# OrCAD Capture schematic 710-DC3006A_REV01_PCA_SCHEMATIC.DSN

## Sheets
1 PAGE1: company: ANALOG DEVICES; note: DEMO BOARD BILL OF MATERIALS; note: NO-OPTO ISOLATED FLYBACK CONVERTER
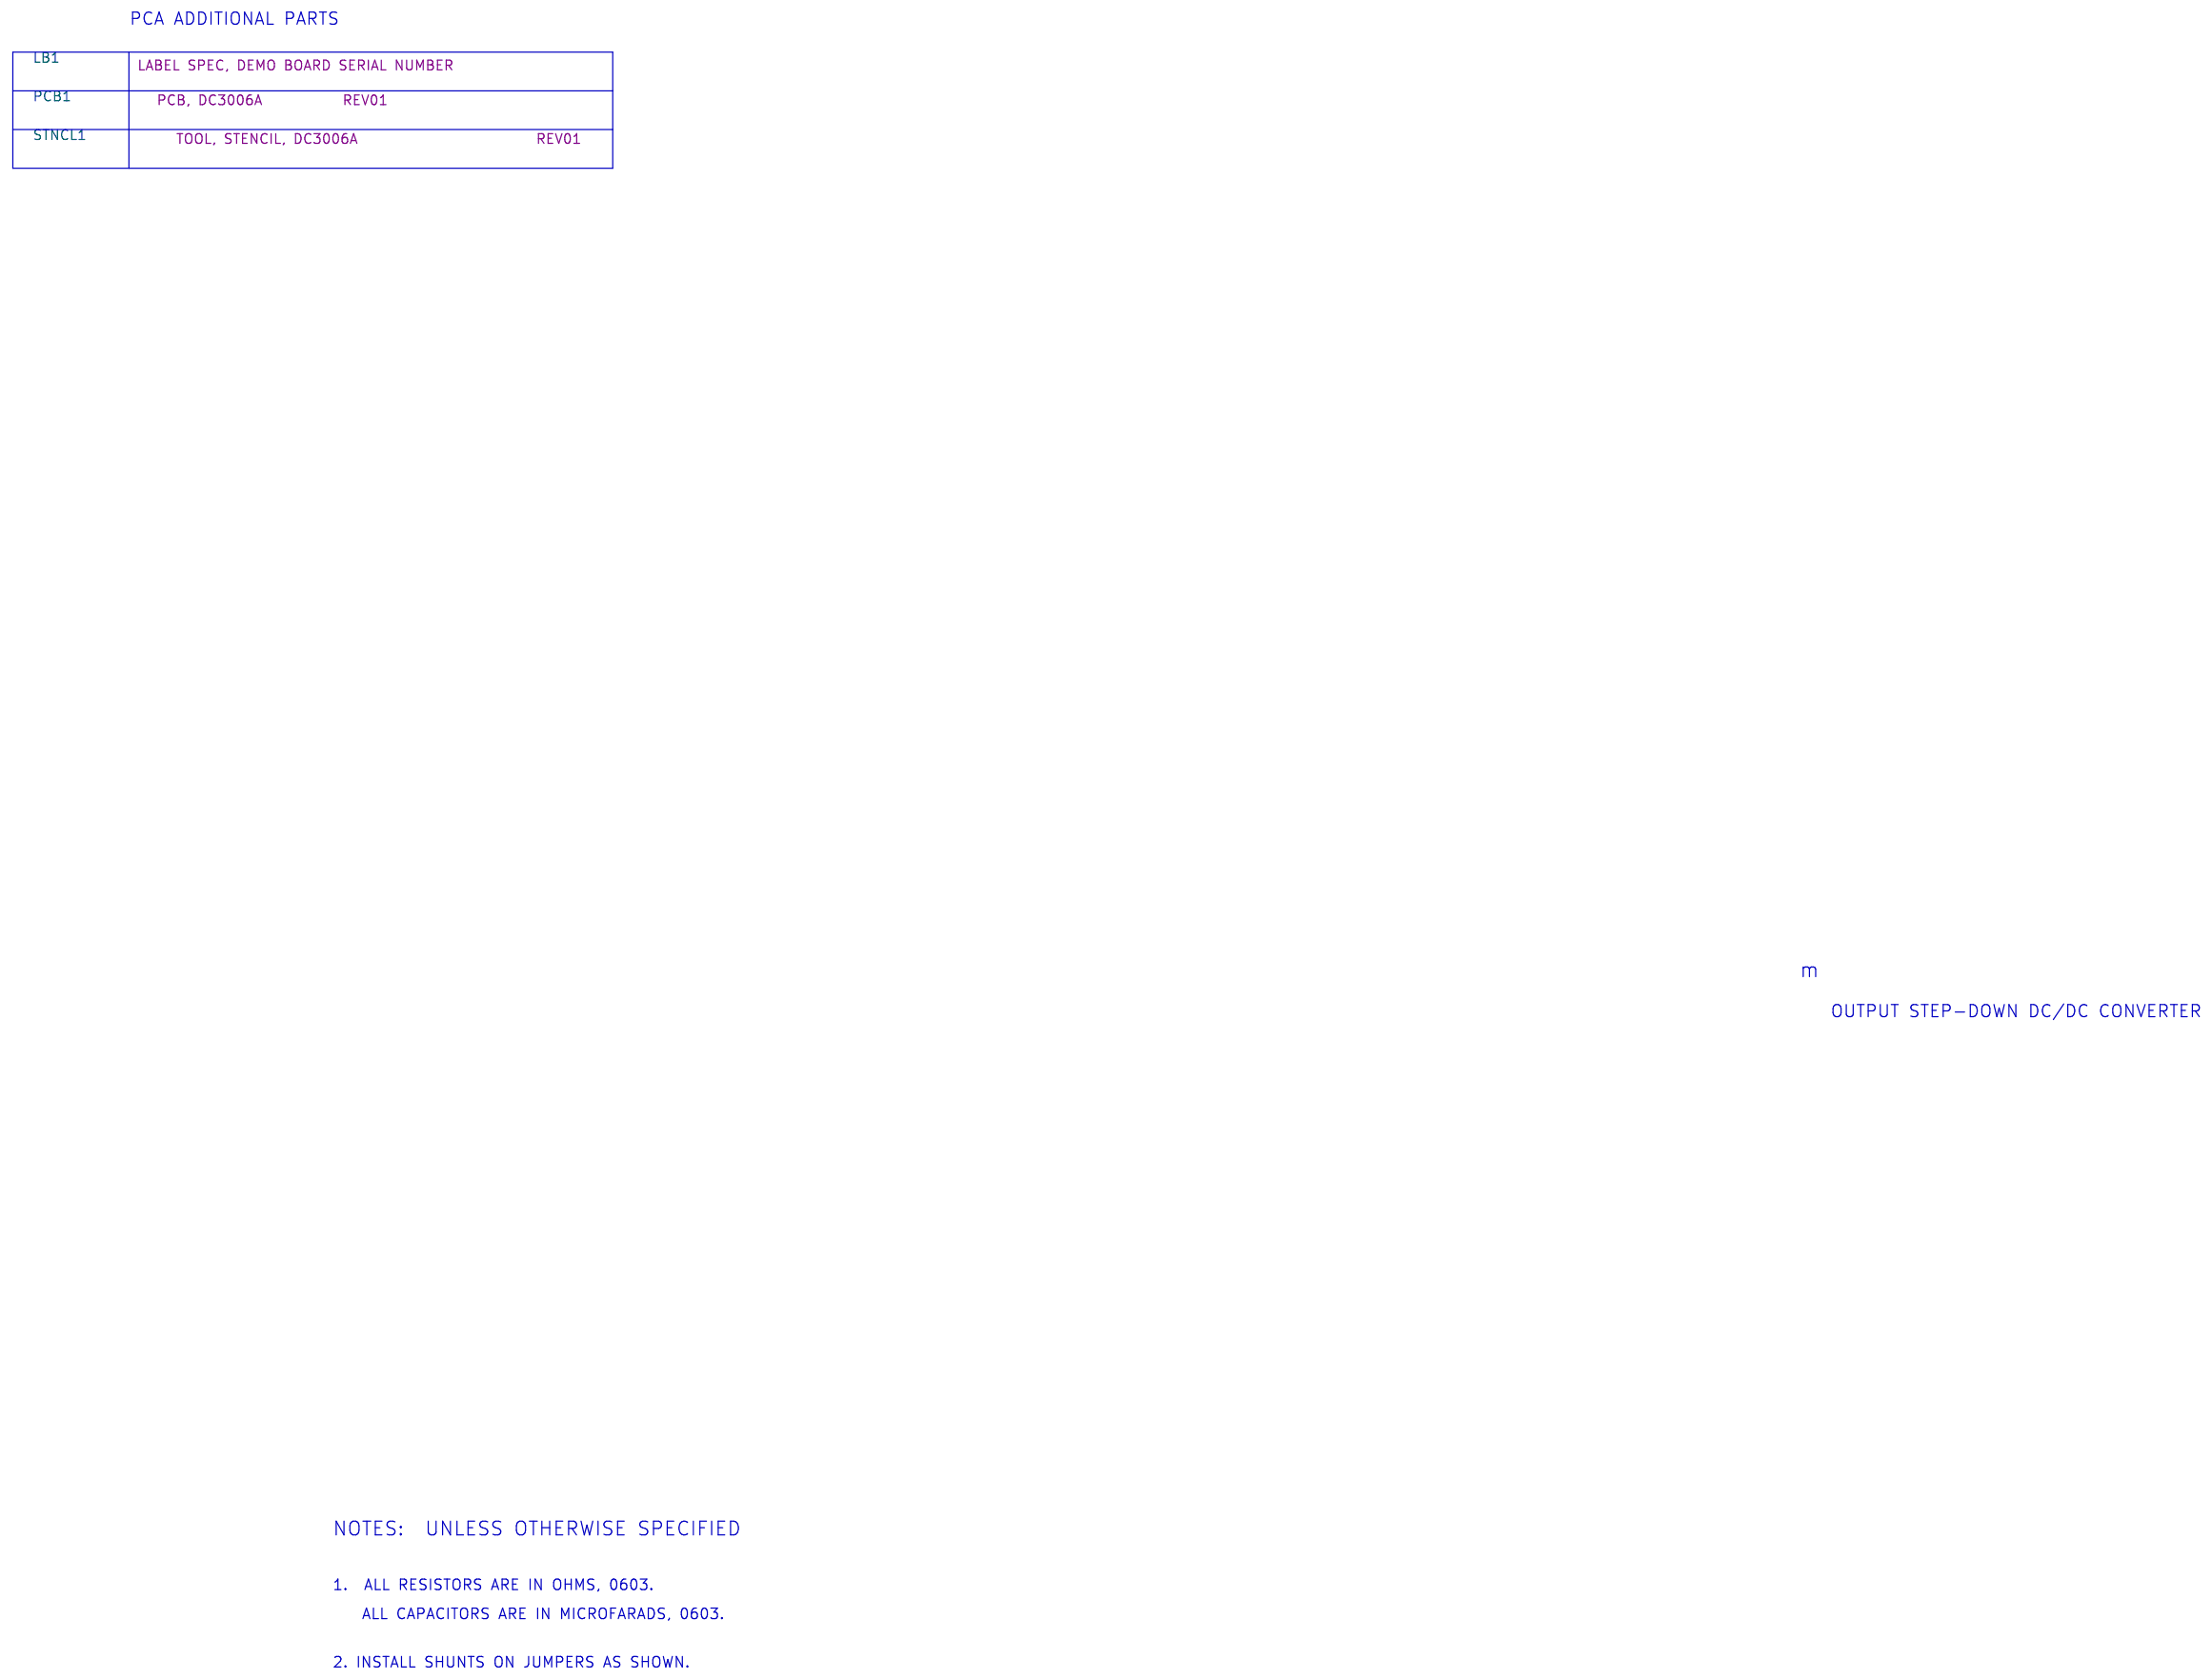
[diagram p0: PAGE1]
2 LT3001ES5: size Custom
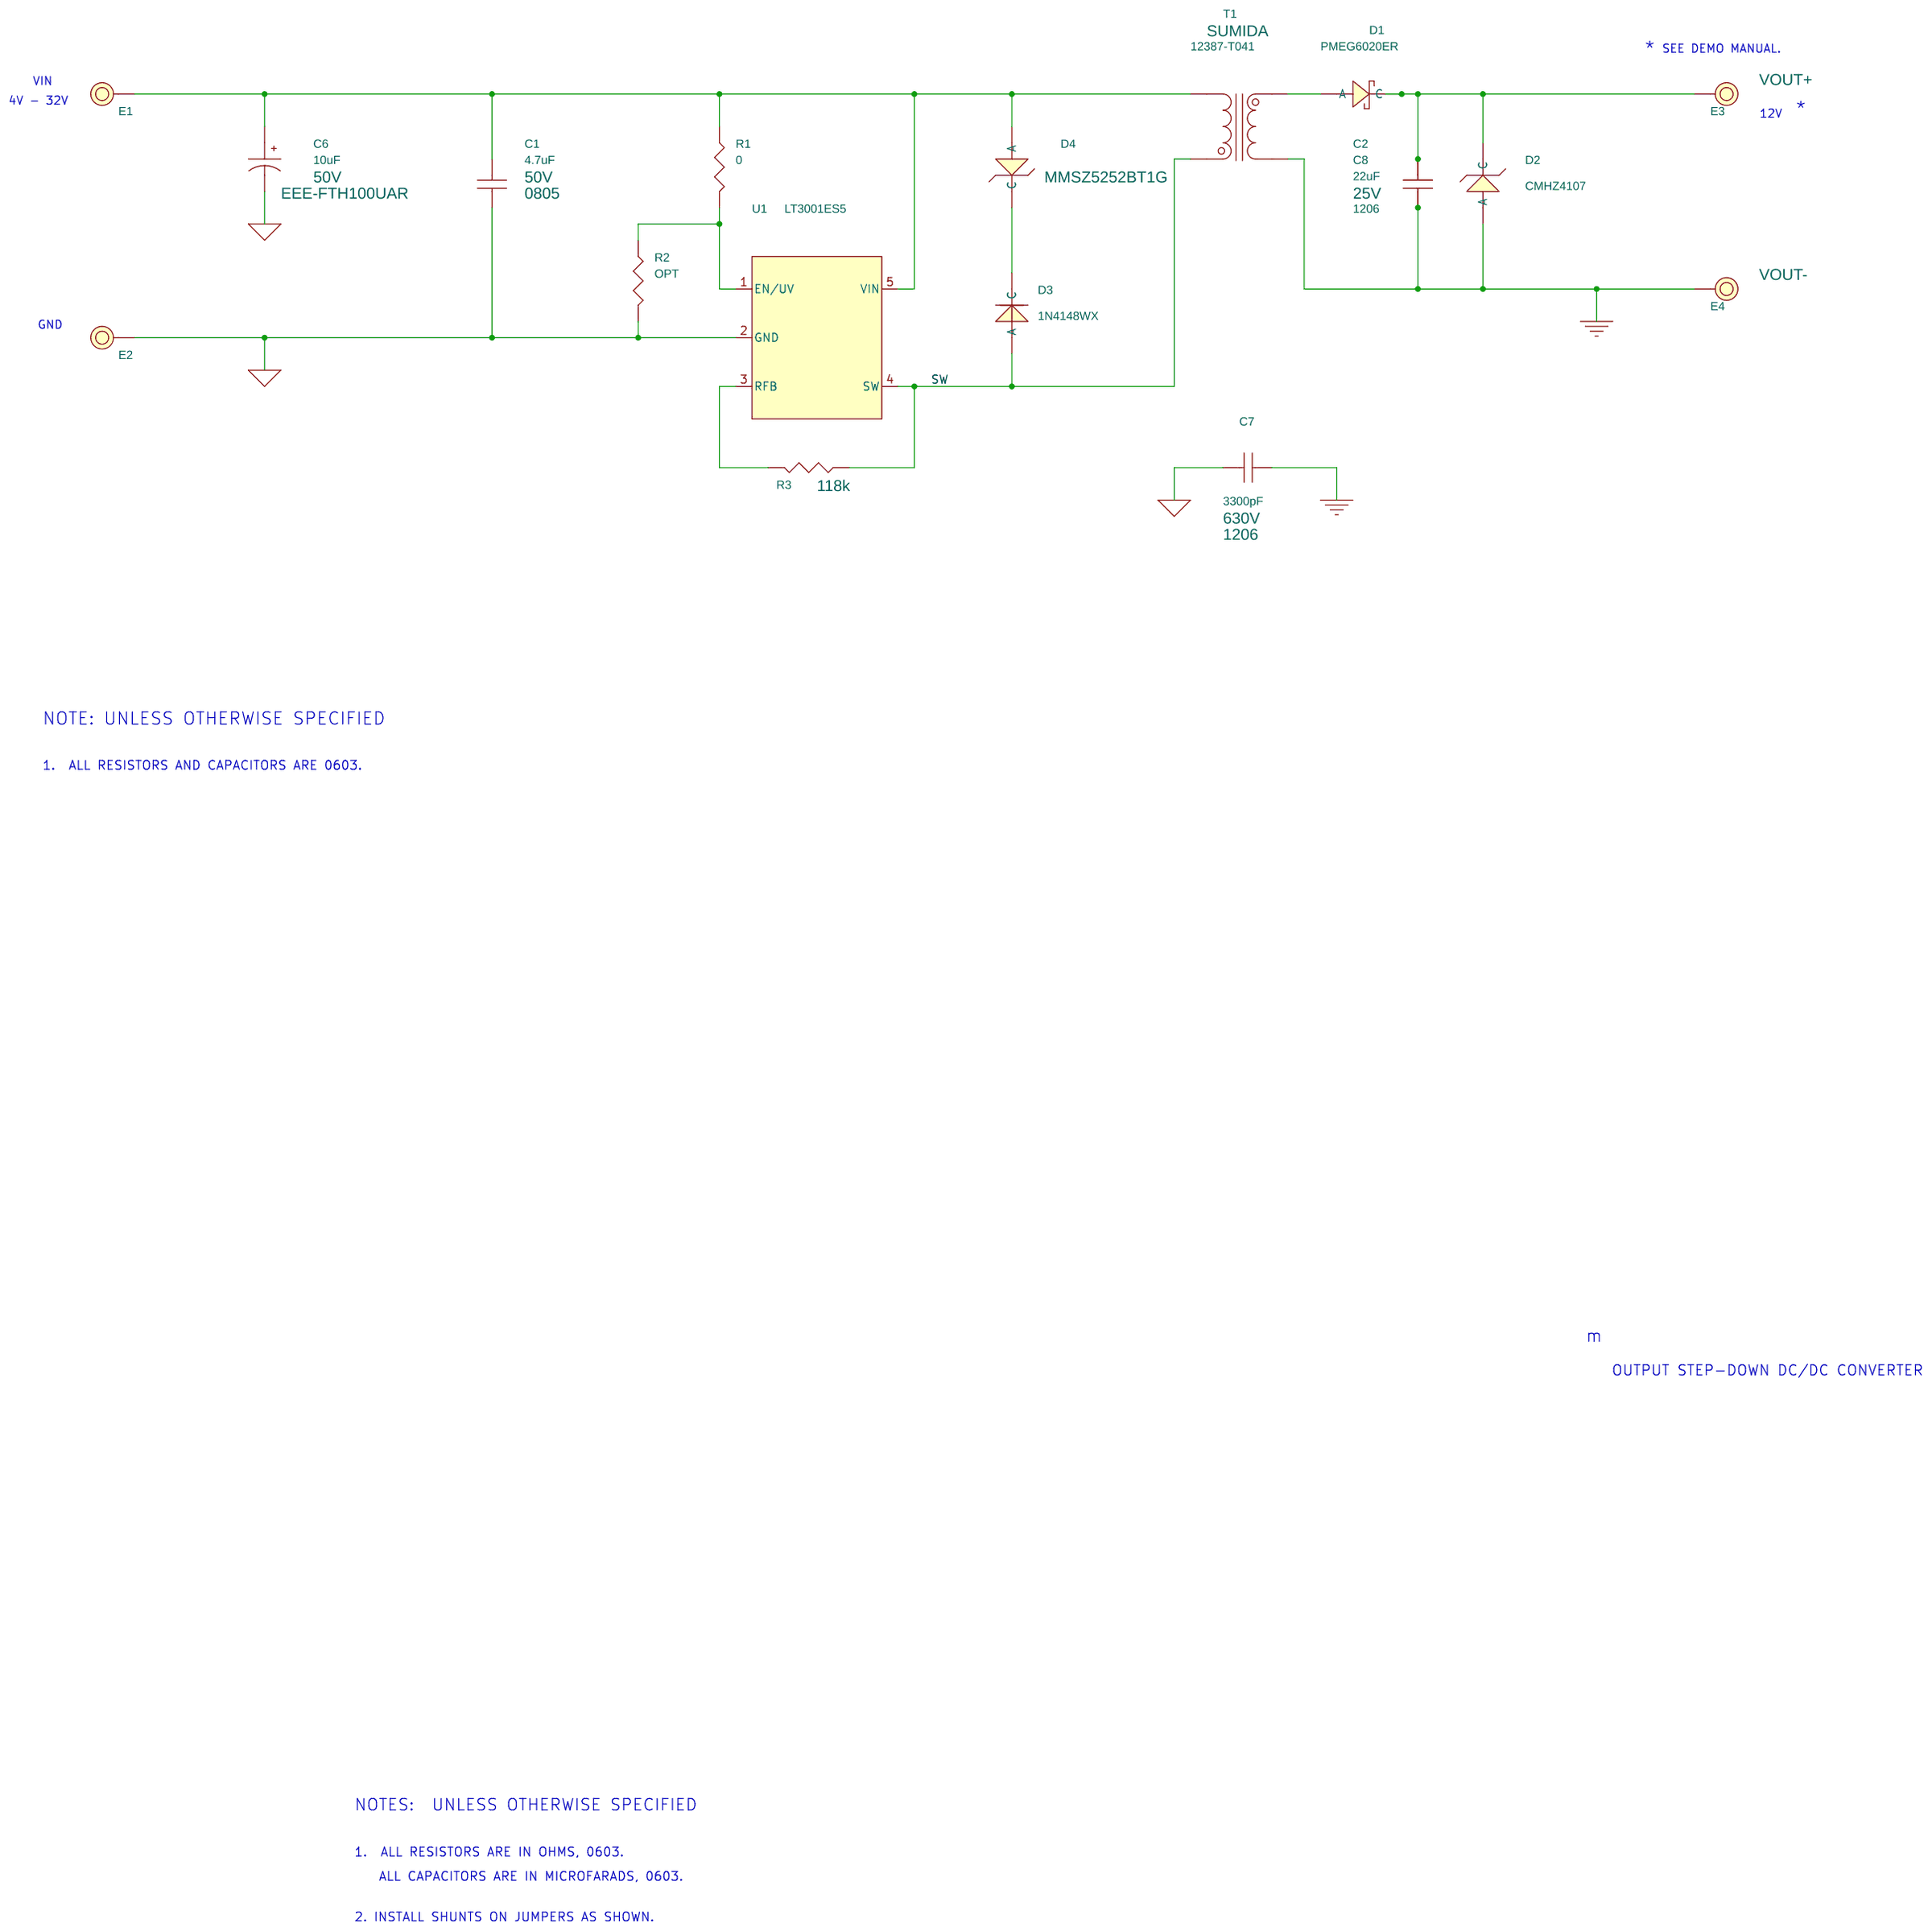
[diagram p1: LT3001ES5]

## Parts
sheet LT3001ES5
C1  4.7uF  [CC0805N]
C2  22uF  [CC1206N]
C6  10uF  [PANASONIC_EFE_4X5.8]
C7  3300pF  [CC1206N]
C8  22uF  [CC1206N]
D1  PMEG6020ER  [SOD-123W-N]
D2  CMHZ4107  [SOD-123N]
D3  1N4148WX  [SOD-323N]
D4  MMSZ5252BT1  [SOD-123N]
E1  TEST POINT  [MILLMAX2501]
E2  TEST POINT  [MILLMAX2501]
E3  TEST POINT  [MILLMAX2501]
E4  TEST POINT  [MILLMAX2501]
R1  0  [CR0603N]
R2  OPT  [CR0603N]
R3  118k  [CR0603N]
T1  12387-T041  [SUMIDA-CEP1110]
U1  LT3001ES5  [LTC-S5-5-1635]
sheet PAGE1
LB1  LABEL  [895-0154_REV01]
PCB1  PCB, DC3006A
STNCL1  TOOL, STENCIL, DC3006A

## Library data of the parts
C1 = CAP: CAP.,4.7uF,X5R,50V,10%,0805; CLASS: DISCRETE; Dielectric Type: X5R; FPLIST: CC0805N,CC0805L,CC0805M; Inventory Qty: 8500; Manufacturer: MURATA; Manufacturer PN: GRM21BR61H475KE51L; PART_NUMBER: 150-0172; Package Size: 0805; Rated Voltage: 50V; Tolerance: 10%
C2 C8 = CAP: CAP.,22uF,X5R,25V,10%,1206; CLASS: DISCRETE; Dielectric Type: X5R; FPLIST: CC1206N,CC1206L,CC1206M; Inventory Qty: 9947; Manufacturer: AVX; Manufacturer PN: 12063D226KAT2A; PART_NUMBER: 150-0253; Package Size: 1206; Part Number: MURATA GRM32ER71A476K; Rated Voltage: 25V; Tolerance: 10%
C6 = CAP_P: CAP.,10uF,ALUM ELECT,50V,20%,RADIAL,4.30mm x 4.30mm,AEC-Q200; CLASS: DISCRETE; Dielectric Type: ALUM ELECT; Inventory Qty: 0; Manufacturer: PANASONIC; Manufacturer PN: EEE-FTH100UAR; PART_NUMBER: 150-0824; Package Size: RADIAL,4.30mm x 4.30mm; Rated Voltage: 50V; Tolerance: 20%
C7 = CAP: CAP.,3300pF,X7R,630V,10%,1206; CLASS: DISCRETE; Dielectric Type: X7R; FPLIST: CC1206N,CC1206M,CC1206L; Inventory Qty: 0; Manufacturer: MURATA; Manufacturer PN: GRM31BR72J332KW01L; PART_NUMBER: 150-0825; Package Size: 1206; Package Type: SMD; Rated Voltage: 630V; Tolerance: 10%
D1 = DIODE_SCHOTTKY_A: DIODE,SCHOTTKY RECT.,2A,60V,CFP3 (SOD-123W),AEC-Q101; CLASS: DISCRETE; FPLIST: SOD-123W-N,SOD-123W-L,SOD-123W-M; Inventory Qty: 0; Manufacturer: NEXPERIA; Manufacturer PN: PMEG6020ER,115; PART_NUMBER: 210-0434; Package Size: SOD123W; Package Type: CFP3 (SOD-123W); Rated Voltage or Zener Voltage: 2A
D2 = ZENER: DIODE,ZENER,13V,5%,500mW,SOD-123; CLASS: DISCRETE; FPLIST: SOD-123N,SOD-123M,SOD-123L; Inventory Qty: 0; Manufacturer: CENTRAL SEMI.; Manufacturer PN: CMHZ4107 TR PBFREE; PART_NUMBER: 210-0498; Package Size: SOD-123; Package Type: SOD-123; Rated Voltage or Zener Voltage: 13V,5%
D3 = DIODE_A: DIODE,GEN PURPOSE,75V,150mA,SOD-323; CLASS: DISCRETE; FPLIST: SOD-323N,SOD-323L,SOD-323M; Inventory Qty: 0; Manufacturer: MICRO COMMERCIAL CO.; Max Forward Current or Rated Power: 150mW; PART_NUMBER: 210-0499; Package Type: SOD-323; Rated Voltage or Zener Voltage: 75V
D4 = ZENER: DIODE,ZENER,24V,500mW,SOD-123; CLASS: DISCRETE; FPLIST: SOD-123N,SOD-123L,SOD-123M; Inventory Qty: 0; Manufacturer: ON SEMICONDUCTOR; Manufacturer PN: MMSZ5252BT1G; Max Forward Current or Rated Power: 500mW; PART_NUMBER: 210-0500; Package Type: SOD-123; Rated Voltage or Zener Voltage: 24V
E1 E2 = TESTPOINT_.219_MILL-MAX_2501: TEST POINT,TURRET,0.094" MTG. HOLE,PCB 0.062" THK; CLASS: IO; FPLIST: MILLMAX2501,MILLMAX2501-2; Inventory Qty: 428822; Manufacturer: MILL-MAX; Manufacturer PN: 2501-2-00-80-00-00-07-0; PART_NUMBER: 260-0003; Part Number: MILL-MAX 2501-2-00-80-00-00-07-0
E3 = TESTPOINT_.219_MILL-MAX_2501: TEST POINT,TURRET,0.094" MTG. HOLE,PCB 0.062" THK; 1ST PART FIELD: VOUT+; CLASS: IO; FPLIST: MILLMAX2501,MILLMAX2501-2; Inventory Qty: 428822; Manufacturer: MILL-MAX; Manufacturer PN: 2501-2-00-80-00-00-07-0; PART_NUMBER: 260-0003; Part Number: MILL-MAX 2501-2-00-80-00-00-07-0
E4 = TESTPOINT_.219_MILL-MAX_2501: TEST POINT,TURRET,0.094" MTG. HOLE,PCB 0.062" THK; 1ST PART FIELD: VOUT-; CLASS: IO; FPLIST: MILLMAX2501,MILLMAX2501-2; Inventory Qty: 428822; Manufacturer: MILL-MAX; Manufacturer PN: 2501-2-00-80-00-00-07-0; PART_NUMBER: 260-0003; Part Number: MILL-MAX 2501-2-00-80-00-00-07-0
R1 = RES: RES.,0 OHM,1/10W,0603,AEC-Q200; CLASS: DISCRETE; FPLIST: CR0603N,CR0603L,CR0603M; Inventory Qty: 576007; Manufacturer: VISHAY; Manufacturer PN: CRCW06030000Z0EA; PART_NUMBER: 100-0009; Package Size: 0603; Rated Power: 1/10W
R2 = RES: RES., OPTION, 0603; CLASS: DISCRETE; FPLIST: CR0603N,CR0603L,CR0603M; PART_NUMBER: 100-2374; Package Size: 0603; Part Number: VISHAY CRCW060393K1FKED; Tol: 1%
R3 = RES: RES.,118k OHMS,1%,1/10W,0603,AEC-Q200; CLASS: DISCRETE; FPLIST: CR0603N,CR0603L,CR0603M; Inventory Qty: 35140; Manufacturer: VISHAY; Manufacturer PN: CRCW0603118KFKEA; PART_NUMBER: 100-0667; Package Size: 0603; Part Number: VISHAY CRCW060384K5FKED; Rated Power: 1/10W; Temperature Coefficient: 100ppm; Tol: 1%; Tolerance: 1%
T1 = SUMIDA-12387-T041: TRANSFORMER,1:1,Np:18-42Vin,Ns:5V with 0.55A,15.5x12.5mm SMD,CEP1110 CUSTOM; CLASS: DISCRETE; Inventory Qty: 0; Manufacturer: SUMIDA; Manufacturer PN: 12387-T041 (CEP1110); PART_NUMBER: 410-0126; Turns Ratio: 1:1
U1 = LT3001-S5: IC,FLYBACK CONVERTER,TSOT-23; CLASS: DISCRETE; Inventory Qty: 0; Manufacturer: ANALOG DEVICES; Manufacturer PN: LT3001ES5#TRPBF; PART_NUMBER: LT3001ES5#TRPBF; Package Type: TSOT-23
LB1 = BLANK_LABEL: LABEL SPEC, DEMO BOARD SERIAL NUMBER; Inventory Qty: 0; Manufacturer: BRADY; Manufacturer PN: THT-96-717-10; PART_NUMBER: 895-0154
PCB1 = BLANK_PCB_PART: BOM Notes: REV01; CLASS: DISCRETE; Inventory Qty: 0; Manufacturer: EAGLE TECH. INC.; Manufacturer PN: 600-DC3006A; PART_NUMBER: 600-DC3006A
STNCL1 = BLANK_STENCIL_PART: BOM Notes: REV01; CLASS: DISCRETE; Inventory Qty: 0; Manufacturer: ANALOG DEVICES; Manufacturer PN: 830-DC3006A; PART_NUMBER: 830-DC3006A

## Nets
DGND: C2.1 C7.1 C8.1 D2.2(A) E4.1 T1.5
GNDSIGNAL: C1.1 C6.2 C7.2 E2.1 R2.2 U1.2(GND)
SW: D3.2(A) R3.2 T1.4 U1.4(SW)
N18174949: C1.2 C6.1 D4.2(A) E1.1 R1.1 T1.1 U1.5(VIN)
N18175089: C2.2 C8.2 D1.1(C) D2.1(C) E3.1
N18175113: R3.1 U1.3(RFB)
N18253108: R1.2 R2.1 U1.1(EN/UV)
N18259639: D3.1(C) D4.1(C)
N18284718: D1.2(A) T1.8

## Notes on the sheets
sheet 1
- PCA ADDITIONAL PARTS
- m
- OUTPUT STEP-DOWN DC/DC CONVERTER
- NOTES:  UNLESS OTHERWISE SPECIFIED
- 1.  ALL RESISTORS ARE IN OHMS, 0603.
- ALL CAPACITORS ARE IN MICROFARADS, 0603.
- 2. INSTALL SHUNTS ON JUMPERS AS SHOWN.
sheet 2
- *
- SEE DEMO MANUAL.
- VIN
- 4V - 32V
- 12V
- *
- GND
- NOTE: UNLESS OTHERWISE SPECIFIED
- 1.  ALL RESISTORS AND CAPACITORS ARE 0603.
- m
- OUTPUT STEP-DOWN DC/DC CONVERTER
- NOTES:  UNLESS OTHERWISE SPECIFIED
- 1.  ALL RESISTORS ARE IN OHMS, 0603.
- ALL CAPACITORS ARE IN MICROFARADS, 0603.
- 2. INSTALL SHUNTS ON JUMPERS AS SHOWN.
